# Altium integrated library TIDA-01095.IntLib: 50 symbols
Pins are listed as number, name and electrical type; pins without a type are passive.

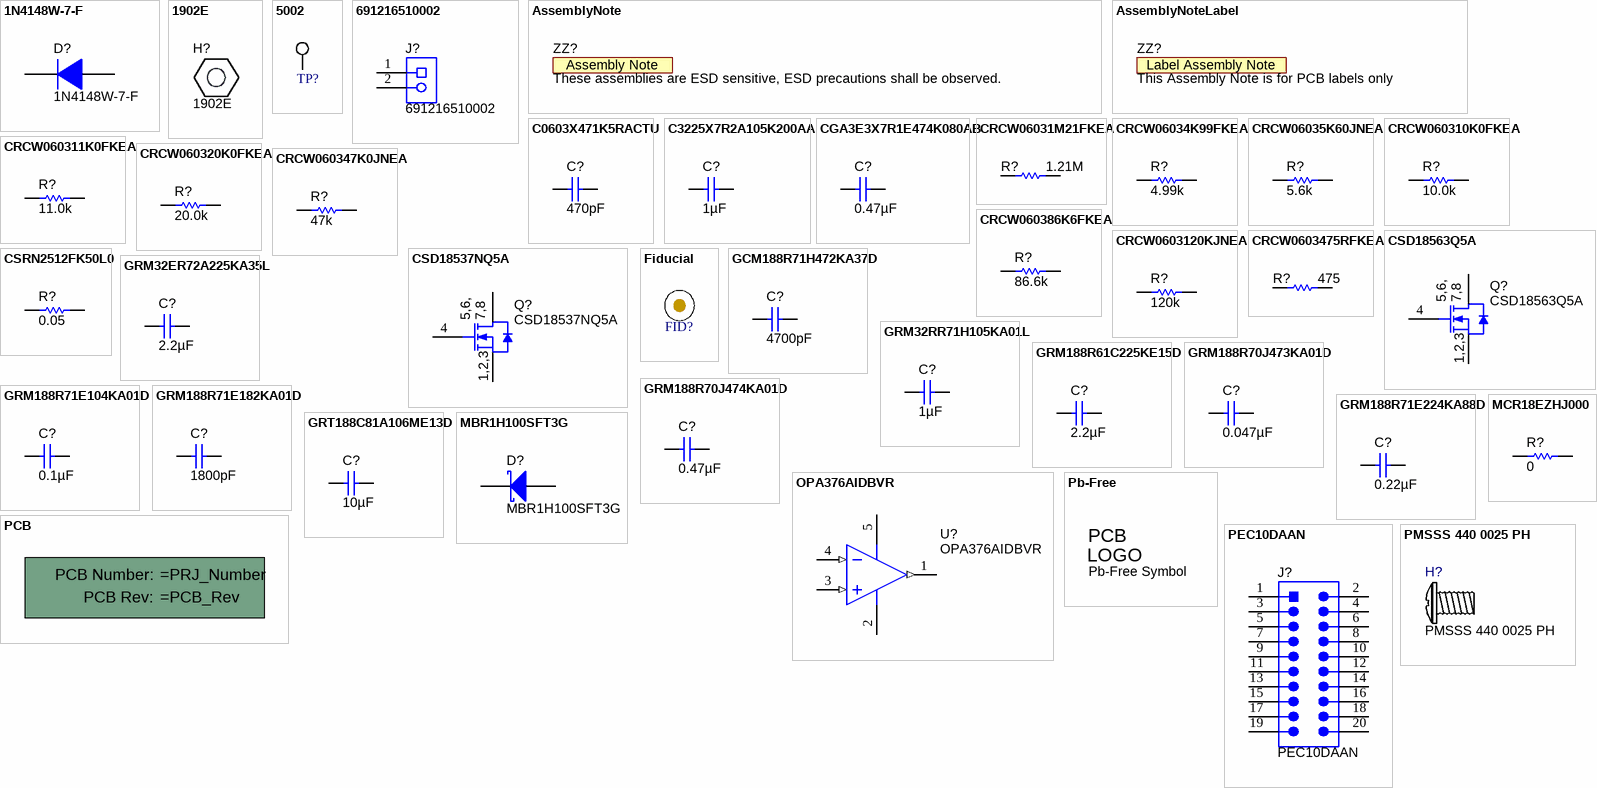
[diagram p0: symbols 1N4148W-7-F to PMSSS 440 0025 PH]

## 1N4148W-7-F
designator D?
Diode, Ultrafast, 100 V, 0.15 A, SOD-123; Manufacturer: Diodes Inc.; U/M: EA; Vf_V: 1.25; Value: 100V; Value1: 0.15A; Value2: 1.25V; Io_A: 0.15; Vr_V: 100; TJmax_C: 150; AEC Category: Q101
signal-integrity model Diode
simulation model 1N4148W
footprint SOD-123
pins: 1 K, 2 A

## 1902E
designator H?
Standoff, Hex, 1"L #4-40 Nylon; Manufacturer: Keystone; CompType: Hardware; SymbolCreator: a0412235
footprint Keystone_1902E

## 5002
designator TP?  (value not drawn)
Test Point, Miniature, White, TH; Manufacturer: Keystone; CompType: Test Point Loop; U/M: EA
footprint Keystone5002
pins: 1

## 691216510002
designator J?
Receptacle, 5.08mm, 2x1, Brass, TH; Manufacturer: Wurth Elektronik; SymbolCreator: a0412235; Pitch_mm: 5.08; Gender: Female; Row_Count: 1; Current_A: 10; Voltage_V: 300; Cert_UL: Y
footprint Wurth_691216510002
pins: 1, 2

## AssemblyNote
designator ZZ?, comment These assemblies are ESD sensitive, ESD precautions shall be observed.  (no BOM)
SymbolCreator: codlsc; CompType: AssemblyNote
footprint AssemblyNote

## AssemblyNoteLabel
designator ZZ?, comment This Assembly Note is for PCB labels only  (no BOM)
SymbolCreator: a0412235
footprint AssemblyNoteLabel

## C0603X471K5RACTU
designator C?  ValueDisplayed: 470pF  (hidden comment: C0603X471K5RACTU)
CAP, CERM, 470 pF, 50 V, +/- 10%, X7R, 0603; Manufacturer: Kemet; Polarized: N; CompType: Capacitor; Value: 470pF; U/M: EA; Cap_F: 0.00000000047; Tolerance_%: 10; Value1: Unknown; VDC_V: 50; Value2: 50V; TaMin_C: -55; TaMax_C: 125; Cap_Case: 0603; AEC Category: Q200
signal-integrity model Cap
simulation model Cap
footprint 0603
footprint 0603M
footprint 0603L
footprint 0603_HV
footprint 0603S
pins: 1, 2

## C3225X7R2A105K200AA
designator C?  ValueDisplayed: 1µF  (hidden comment: C3225X7R2A105K200AA)
CAP, CERM, 1 µF, 100 V, +/- 10%, X7R, 1210; Manufacturer: TDK; Polarized: N; CompType: Capacitor; Value: 1uF; U/M: EA; Cap_F: 0.000001; Tolerance_%: 10; Value1: Unknown; VDC_V: 100; Value2: 100V; TaMin_C: -55; TaMax_C: 125; Cap_Case: 1210; AEC Category: Q200
signal-integrity model Cap
simulation model Cap
footprint 1210
footprint 1210M
footprint 1210L
pins: 1, 2

## CGA3E3X7R1E474K080AB
designator C?  ValueDisplayed: 0.47µF  (hidden comment: CGA3E3X7R1E474K080AB)
CAP, CERM, 0.47 µF, 25 V, +/- 10%, X7R, AEC-Q200 Grade 1, 0603; Manufacturer: TDK; Polarized: N; CompType: Capacitor; Value: 0.47uF; U/M: EA; Cap_F: 0.00000047; Tolerance_%: 10; Value1: Unknown; VDC_V: 25; Value2: 25V; TaMin_C: -55; TaMax_C: 125; Cap_Case: 0603; AEC Category: Q200; AEC Qualified: Y; AEC Grade: 1
signal-integrity model Cap
simulation model Cap
footprint 0603
footprint 0603M
footprint 0603L
footprint 0603_HV
footprint 0603S
pins: 1, 2

## CRCW06031M21FKEA
designator R?  ValueDisplayed: 1.21M  (hidden comment: CRCW06031M21FKEA)
RES, 1.21 M, 1%, 0.1 W, 0603; Manufacturer: Vishay-Dale; CompType: Resistor; Value: 1.21Meg; Res_ohm: 1210000; Value_Code: 1M21; Tolerance_%: 1; Power_W: 0.1; Value2: 0.1W; VDC_V: 75; TempCo: 100 ppm/C; EIA_Code: E96; U/M: EA; AEC Category: Q200
signal-integrity model Resistor
simulation model Resistor
footprint 0603
footprint 0603M
footprint 0603L
footprint 0603_HV
footprint 0603S
pins: 1, 2

## CRCW06034K99FKEA
designator R?  ValueDisplayed: 4.99k  (hidden comment: CRCW06034K99FKEA)
RES, 4.99 k, 1%, 0.1 W, 0603; Manufacturer: Vishay-Dale; CompType: Resistor; Value: 4.99k; Res_ohm: 4990; Value_Code: 4k99; Tolerance_%: 1; Power_W: 0.1; Value2: 0.1W; VDC_V: 75; TempCo: 100 ppm/C; EIA_Code: E96; U/M: EA; AEC Category: Q200; SizeArea_mm2: 1.28; SizeX_mm: 1.6; SizeY_mm: 0.8
signal-integrity model Resistor
simulation model Resistor
footprint 0603
footprint 0603M
footprint 0603L
footprint 0603_HV
footprint 0603S
pins: 1, 2

## CRCW06035K60JNEA
designator R?  ValueDisplayed: 5.6k  (hidden comment: CRCW06035K60JNEA)
RES, 5.6 k, 5%, 0.1 W, 0603; Manufacturer: Vishay-Dale; CompType: Resistor; Value: 5.6k; Res_ohm: 5600; Value_Code: 5k60; Tolerance_%: 5; Power_W: 0.1; Value2: 0.1W; VDC_V: 75; TempCo: 200 ppm/C; EIA_Code: E24; U/M: EA; AEC Category: Q200; SizeArea_mm2: 1.28; SizeX_mm: 1.6; SizeY_mm: 0.8; SizeZ_mm: 1
signal-integrity model Resistor
simulation model Resistor
footprint 0603
footprint 0603M
footprint 0603L
footprint 0603_HV
footprint 0603S
pins: 1, 2

## CRCW060310K0FKEA
designator R?  ValueDisplayed: 10.0k  (hidden comment: CRCW060310K0FKEA)
RES, 10.0 k, 1%, 0.1 W, 0603; Manufacturer: Vishay-Dale; CompType: Resistor; Value: 10.0k; Res_ohm: 10000; Value_Code: 10k0; Tolerance_%: 1; Power_W: 0.1; Value2: 0.1W; VDC_V: 75; TempCo: 100 ppm/C; EIA_Code: E96; U/M: EA; AEC Category: Q200
signal-integrity model Resistor
simulation model Resistor
footprint 0603
footprint 0603M
footprint 0603L
footprint 0603_HV
footprint 0603S
pins: 1, 2

## CRCW060311K0FKEA
designator R?  ValueDisplayed: 11.0k  (hidden comment: CRCW060311K0FKEA)
RES, 11.0 k, 1%, 0.1 W, 0603; Manufacturer: Vishay-Dale; CompType: Resistor; Value: 11.0k; Res_ohm: 11000; Value_Code: 11k0; Tolerance_%: 1; Power_W: 0.1; Value2: 0.1W; VDC_V: 75; TempCo: 100 ppm/C; EIA_Code: E96; U/M: EA; AEC Category: Q200; SizeArea_mm2: 1.28; SizeX_mm: 1.6; SizeY_mm: 0.8
signal-integrity model Resistor
simulation model Resistor
footprint 0603
footprint 0603M
footprint 0603L
footprint 0603_HV
footprint 0603S
pins: 1, 2

## CRCW060320K0FKEA
designator R?  ValueDisplayed: 20.0k  (hidden comment: CRCW060320K0FKEA)
RES, 20.0 k, 1%, 0.1 W, 0603; Manufacturer: Vishay-Dale; CompType: Resistor; Value: 20.0k; Res_ohm: 20000; Value_Code: 20k0; Tolerance_%: 1; Power_W: 0.1; Value2: 0.1W; VDC_V: 75; TempCo: 100 ppm/C; EIA_Code: E96; U/M: EA; AEC Category: Q200
signal-integrity model Resistor
simulation model Resistor
footprint 0603
footprint 0603M
footprint 0603L
footprint 0603_HV
footprint 0603S
pins: 1, 2

## CRCW060347K0JNEA
designator R?  ValueDisplayed: 47k  (hidden comment: CRCW060347K0JNEA)
RES, 47 k, 5%, 0.1 W, 0603; Manufacturer: Vishay-Dale; CompType: Resistor; Value: 47k; Res_ohm: 47000; Value_Code: 47k0; Tolerance_%: 5; Power_W: 0.1; Value2: 0.1W; VDC_V: 75; TempCo: 200 ppm/C; EIA_Code: E24; U/M: EA; AEC Category: Q200; SizeArea_mm2: 1.28; SizeX_mm: 1.6; SizeY_mm: 0.8; SizeZ_mm: 1
signal-integrity model Resistor
simulation model Resistor
footprint 0603
footprint 0603M
footprint 0603L
footprint 0603_HV
footprint 0603S
pins: 1, 2

## CRCW060386K6FKEA
designator R?  ValueDisplayed: 86.6k  (hidden comment: CRCW060386K6FKEA)
RES, 86.6 k, 1%, 0.1 W, 0603; Manufacturer: Vishay-Dale; CompType: Resistor; Value: 86.6k; Res_ohm: 86600; Value_Code: 86k6; Tolerance_%: 1; Power_W: 0.1; Value2: 0.1W; VDC_V: 75; TempCo: 100 ppm/C; EIA_Code: E96; U/M: EA; AEC Category: Q200
signal-integrity model Resistor
simulation model Resistor
footprint 0603
footprint 0603M
footprint 0603L
footprint 0603_HV
footprint 0603S
pins: 1, 2

## CRCW0603120KJNEA
designator R?  ValueDisplayed: 120k  (hidden comment: CRCW0603120KJNEA)
RES, 120 k, 5%, 0.1 W, 0603; Manufacturer: Vishay-Dale; CompType: Resistor; Value: 120k; Res_ohm: 120000; Tolerance_%: 5; Power_W: 0.1; Value2: 0.1W; VDC_V: 75; TempCo: 200 ppm/C; EIA_Code: E24; U/M: EA; AEC Category: Q200; SizeArea_mm2: 1.28; SizeX_mm: 1.6; SizeY_mm: 0.8; SizeZ_mm: 1
signal-integrity model Resistor
simulation model Resistor
footprint 0603
footprint 0603M
footprint 0603L
footprint 0603_HV
footprint 0603S
pins: 1, 2

## CRCW0603475RFKEA
designator R?  ValueDisplayed: 475  (hidden comment: CRCW0603475RFKEA)
RES, 475, 1%, 0.1 W, 0603; Manufacturer: Vishay-Dale; CompType: Resistor; Value: 475; Value_Code: 475R; Tolerance_%: 1; Power_W: 0.1; Value2: 0.1W; VDC_V: 75; TempCo: 100 ppm/C; EIA_Code: E96; U/M: EA; AEC Category: Q200
signal-integrity model Resistor
simulation model Resistor
footprint 0603
footprint 0603M
footprint 0603L
footprint 0603_HV
footprint 0603S
pins: 1, 2

## CSD18537NQ5A
designator Q?
MOSFET, N-CH, 60 V, 50 A, SON 5x6mm; Manufacturer: Texas Instruments; Alternate Manufacturer: None; U/M: EA; ChType: N; Value: 60V; VdsMax_V: 60; Value1: 0.036 ohm; Rdson45_ohm: 0.036; Value2: 14 nC; QgTyp_nC: 14; Vgs_V: 20; IdsMax_A: 50; AEC Category: Q101; SizeAreaWB_mm2: 55.2; SizeArea_mm2: 29.4; SizeX_mm: 6; SizeY_mm: 4.9; SizeZ_mm: 1
footprint TRANS_NexFET_Q5A
pins: 1 S, 2 S, 3 S, 4 G, 5 D, 6 D, 7 D, 8 D, 9 D

## CSD18563Q5A
designator Q?
MOSFET, N-CH, 60 V, 15 A, SON 5x6mm; Manufacturer: Texas Instruments; Alternate Manufacturer: None; U/M: EA; ChType: N; Value: 60V; VdsMax_V: 60; Value1: 0.0086 ohm; Rdson45_ohm: 0.0086; Value2: 15 nC; QgTyp_nC: 15; Vgs_V: 20; AEC Category: Q101
footprint TRANS_NexFET_Q5A
pins: 1 S, 2 S, 3 S, 4 G, 5 D, 6 D, 7 D, 8 D, 9 D

## CSRN2512FK50L0
designator R?  ValueDisplayed: 0.05  (hidden comment: CSRN2512FK50L0)
RES, 0.05, 1%, 2 W, 2512; Manufacturer: Stackpole Electronics Inc; CompType: Resistor; Value: 0.05; Value_Code: R050; Tolerance_%: 1; Power_W: 2; Value2: 2W; TempCo: 200 ppm/C; EIA_Code: E96; U/M: EA; AEC Category: Q200
signal-integrity model Resistor
simulation model Resistor
footprint 2512
footprint 2512M
footprint 2512L
pins: 1, 2

## Fiducial
designator FID?  (value not drawn)
Fiducial mark.  There is nothing to buy or mount.; SymbolCreator: codlsc
footprint Fiducial10-30
footprint Fiducial10-20
footprint Fiducial15-30
footprint Fiducial20-40
footprint Fiducial6.4-20

## GCM188R71H472KA37D
designator C?  ValueDisplayed: 4700pF  (hidden comment: GCM188R71H472KA37D)
CAP, CERM, 4700 pF, 50 V, +/- 10%, X7R, AEC-Q200 Grade 1, 0603; Manufacturer: MuRata; Polarized: N; CompType: Capacitor; Value: 4700pF; U/M: EA; Cap_F: 0.0000000047; Tolerance_%: 10; Value1: Unknown; VDC_V: 50; Value2: 50V; TaMin_C: -55; TaMax_C: 125; Cap_Case: 0603; AEC Category: Q200; AEC Qualified: Y; AEC Grade: 1
signal-integrity model Cap
simulation model Cap
footprint 0603
footprint 0603M
footprint 0603L
footprint 0603_HV
footprint 0603S
pins: 1, 2

## GRM32ER72A225KA35L
designator C?  ValueDisplayed: 2.2µF  (hidden comment: GRM32ER72A225KA35L)
CAP, CERM, 2.2 µF, 100 V, +/- 10%, X7R, 1210; Manufacturer: MuRata; Polarized: N; CompType: Capacitor; Value: 2.2uF; U/M: EA; Cap_F: 0.0000022; Tolerance_%: 10; ESR_ohm: 0.007; Value1: 0.007 ohm; VDC_V: 100; Value2: 100V; IRMS_A: 4.4; TaMin_C: -55; TaMax_C: 125; Cap_Case: 1210; AEC Category: Q200
signal-integrity model Cap
simulation model Cap
footprint 1210_270
footprint 1210_270M
footprint 1210_270L
pins: 1, 2

## GRM32RR71H105KA01L
designator C?  ValueDisplayed: 1µF  (hidden comment: GRM32RR71H105KA01L)
CAP, CERM, 1 µF, 50 V, +/- 10%, X7R, 1210; Manufacturer: MuRata; Polarized: N; CompType: Capacitor; Value: 1uF; U/M: EA; Cap_F: 0.000001; Tolerance_%: 10; ESR_ohm: 0.003; Value1: 0.003 ohm; VDC_V: 50; Value2: 50V; TaMin_C: -55; TaMax_C: 125; Cap_Case: 1210; AEC Category: Q200
signal-integrity model Cap
simulation model Cap
footprint 1210_200
footprint 1210_200M
footprint 1210_200L
pins: 1, 2

## GRM188R61C225KE15D
designator C?  ValueDisplayed: 2.2µF  (hidden comment: GRM188R61C225KE15D)
CAP, CERM, 2.2 µF, 16 V, +/- 10%, X5R, 0603; Manufacturer: MuRata; Polarized: N; CompType: Capacitor; Value: 2.2uF; U/M: EA; Cap_F: 0.0000022; Tolerance_%: 10; Value1: Unknown; VDC_V: 16; Value2: 16V; TaMin_C: -55; TaMax_C: 85; Cap_Case: 0603; AEC Category: Q200
signal-integrity model Cap
simulation model Cap
footprint 0603
footprint 0603M
footprint 0603L
footprint 0603_HV
footprint 0603S
pins: 1, 2

## GRM188R70J473KA01D
designator C?  ValueDisplayed: 0.047µF  (hidden comment: GRM188R70J473KA01D)
CAP, CERM, 0.047 µF, 6.3 V, +/- 10%, X7R, 0603; Manufacturer: MuRata; Polarized: N; CompType: Capacitor; Value: 0.047uF; U/M: EA; Cap_F: 0.000000047; Tolerance_%: 10; Value1: Unknown; VDC_V: 6.3; Value2: 6.3V; TaMin_C: -55; TaMax_C: 125; Cap_Case: 0603; AEC Category: Q200
signal-integrity model Cap
simulation model Cap
footprint 0603
footprint 0603M
footprint 0603L
footprint 0603_HV
footprint 0603S
pins: 1, 2

## GRM188R70J474KA01D
designator C?  ValueDisplayed: 0.47µF  (hidden comment: GRM188R70J474KA01D)
CAP, CERM, 0.47 µF, 6.3 V, +/- 10%, X7R, 0603; Manufacturer: MuRata; Polarized: N; CompType: Capacitor; Value: 0.47uF; U/M: EA; Cap_F: 0.00000047; Tolerance_%: 10; Value1: Unknown; VDC_V: 6.3; Value2: 6.3V; TaMin_C: -55; TaMax_C: 125; Cap_Case: 0603; AEC Category: Q200
signal-integrity model Cap
simulation model Cap
footprint 0603
footprint 0603M
footprint 0603L
footprint 0603_HV
footprint 0603S
pins: 1, 2

## GRM188R71E104KA01D
designator C?  ValueDisplayed: 0.1µF  (hidden comment: GRM188R71E104KA01D)
CAP, CERM, 0.1 µF, 25 V, +/- 10%, X7R, 0603; Manufacturer: MuRata; Polarized: N; CompType: Capacitor; Value: 0.1uF; U/M: EA; Cap_F: 0.0000001; Tolerance_%: 10; Value1: Unknown; VDC_V: 25; Value2: 25V; TaMin_C: -55; TaMax_C: 125; Cap_Case: 0603; AEC Category: Q200
signal-integrity model Cap
simulation model Cap
footprint 0603
footprint 0603M
footprint 0603L
footprint 0603_HV
footprint 0603S
pins: 1, 2

## GRM188R71E182KA01D
designator C?  ValueDisplayed: 1800pF  (hidden comment: GRM188R71E182KA01D)
CAP, CERM, 1800 pF, 25 V, +/- 10%, X7R, 0603; Manufacturer: MuRata; Polarized: N; CompType: Capacitor; Value: 1800pF; U/M: EA; Cap_F: 0.0000000018; Tolerance_%: 10; Value1: Unknown; VDC_V: 25; Value2: 25V; TaMin_C: -55; TaMax_C: 125; Cap_Case: 0603; AEC Category: Q200; SizeArea_mm2: 1.28; SizeAreaWB_mm2: 4.68; SizeX_mm: 1.6; SizeY_mm: 0.8; SizeZ_mm: 1
signal-integrity model Cap
simulation model Cap
footprint 0603
footprint 0603M
footprint 0603L
footprint 0603_HV
footprint 0603S
pins: 1, 2

## GRM188R71E224KA88D
designator C?  ValueDisplayed: 0.22µF  (hidden comment: GRM188R71E224KA88D)
CAP, CERM, 0.22 µF, 25 V, +/- 10%, X7R, 0603; Manufacturer: MuRata; Polarized: N; CompType: Capacitor; Value: 0.22uF; U/M: EA; Cap_F: 0.00000022; Tolerance_%: 10; Value1: Unknown; VDC_V: 25; Value2: 25V; TaMin_C: -55; TaMax_C: 125; Cap_Case: 0603; AEC Category: Q200
signal-integrity model Cap
simulation model Cap
footprint 0603
footprint 0603M
footprint 0603L
footprint 0603_HV
footprint 0603S
pins: 1, 2

## GRT188C81A106ME13D
designator C?  ValueDisplayed: 10µF  (hidden comment: GRT188C81A106ME13D)
CAP, CERM, 10 µF, 10 V, +/- 20%, X6S, AEC-Q200 Grade 2, 0603; Manufacturer: MuRata; Polarized: N; CompType: Capacitor; Value: 10uF; U/M: EA; Cap_F: 0.00001; Tolerance_%: 20; Value1: Unknown; VDC_V: 10; Value2: 10V; TaMin_C: -55; TaMax_C: 105; Cap_Case: 0603; AEC Category: Q200; AEC Qualified: Y; AEC Grade: 2
signal-integrity model Cap
simulation model Cap
footprint 0603
footprint 0603M
footprint 0603L
footprint 0603_HV
footprint 0603S
pins: 1, 2

## MBR1H100SFT3G
designator D?
Diode, Schottky, 100 V, 1 A, SOD-123FL; Manufacturer: ON Semiconductor; U/M: EA; Vf_V: 0.76; Value: 100V; Value1: 1A; Value2: 0.76V; Io_A: 1; Vr_V: 100; TJmax_C: 175; RJC_CperW: 85; SizeAreaWB_mm2: 13.44; SizeArea_mm2: 6.84; SizeX_mm: 3.8; SizeY_mm: 1.8; AEC Category: Q101
signal-integrity model Diode
footprint SOD-123FL
pins: 1 K, 2 A

## MCR18EZHJ000
designator R?  ValueDisplayed: 0  (hidden comment: MCR18EZHJ000)
RES, 0, 5%, 0.25 W, 1206; Manufacturer: Rohm; CompType: Resistor; Value: 0; Value_Code: 0000; Tolerance_%: 5; Power_W: 0.25; Value2: 0.25W; VDC_V: 200; TempCo: 200 ppm/C; EIA_Code: E24; U/M: EA; AEC Category: Q200
signal-integrity model Resistor
simulation model Resistor
footprint 1206
footprint 1206M
footprint 1206L
pins: 1, 2

## OPA376AIDBVR
designator U?
Precision, Low Noise, Low Iq Operational Amplifier, 2.2 to 5.5 V, -40 to 125 degC, 5-pin SOT23 (DBV0005A), Green (RoHS & no Sb/Br); Manufacturer: Texas Instruments; Alternate PartNumber: Equivalent; CMRR(Min)(dB): 76; IIB(Max)(pA): 10; Iq per channel(Max)(mA): 0.95; Number of Channels: 1; Offset Drift(Typ)(uV/C): 0.32; Slew Rate(Typ)(V/us): 2; Sub Family: Low Input Bias Current Amp (<=10pA), Low Noise Amp (<=10nV/rtHz), Low Offset Voltage Amplifier (<=500uV), Low Supply Voltage Amplifier (<=2.7V), Precision Amplifier; Total Supply Voltage(Max)(+5V is 5, +/-5V is 10): 5.5; Total Supply Voltage(Min)(+5V is 5, +/-5V is 10): 2.2; Vio (25C)(Max)(mV): 0.025; Vn at 1kHz(Typ)(nV/rtHz): 7.5
footprint DBV0005A_N (SOT23, 5-Leads, Body 2.9x1.6mm, Pitch 0.95mm, IPC Medium Density)
footprint DBV0005A_L (SOT23, 5-Leads, Body 2.9x1.6mm, Pitch 0.95mm, IPC Low Density)
footprint DBV0005A_M (SOT23, 5-Leads, Body 2.9x1.6mm, Pitch 0.95mm, IPC Low Density)
pins: 1 OUT (out), 2 V- (power), 3 IN+ (in), 4 IN- (in), 5 V+ (power)

## Pb-Free
designator Logo?, comment Pb-Free Symbol  (no BOM)
SymbolCreator: a0412235
footprint Pb-Free_Overlay_Medium
footprint Pb-Free_Overlay_Small

## PCB
designator !PCB?, comment Printed Circuit Board  (value not drawn)  (mechanical)
Manufacturer: Any; SymbolCreator: a0412235; CompType: PCB
1 alternate drawing of the same symbol

## PEC10DAAN
designator J?
Header, 100mil, 10x2, TH; Manufacturer: Sullins Connector Solutions; SymbolCreator: a0412235; U/M: EA
footprint SULLINS_PEC10DAAN
pins: 1, 2, 3, 4, 5, 6, 7, 8, 9, 10, 11, 12, 13, 14, 15, 16, 17, 18, 19, 20

## PMSSS 440 0025 PH
designator H?
MACHINE SCREW PAN PHILLIPS 4-40; Manufacturer: B&F Fastener Supply; CompType: Standoff; SymbolCreator: a0412235
footprint B_F_PMSSS4400025PH

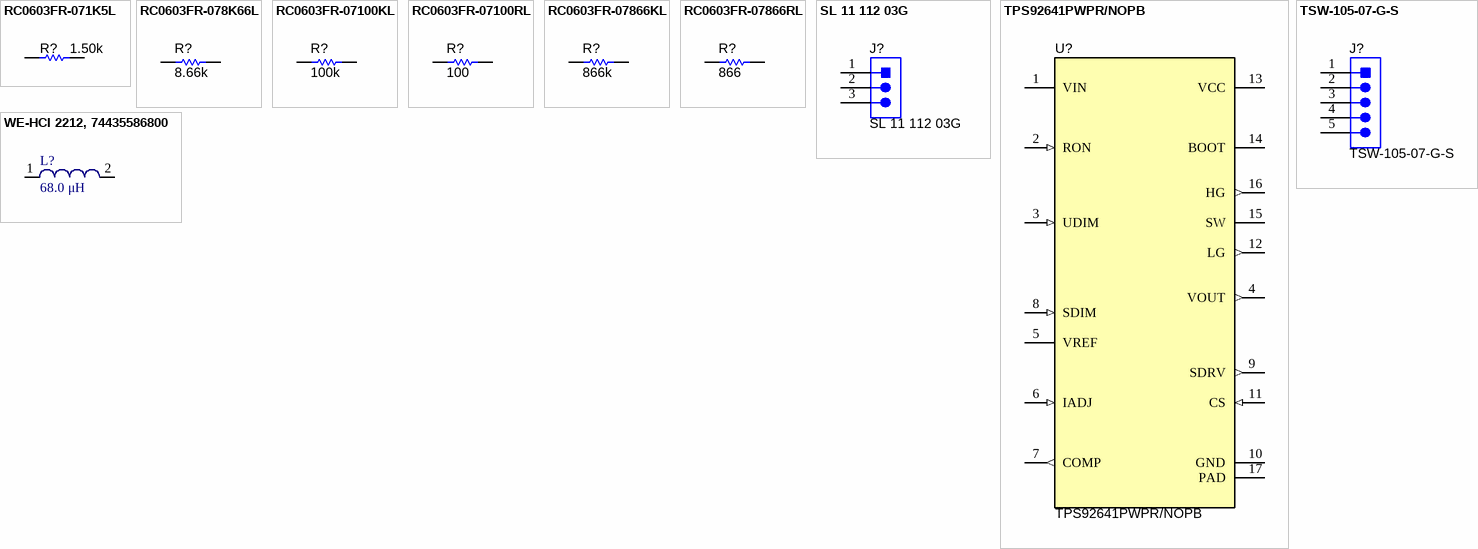
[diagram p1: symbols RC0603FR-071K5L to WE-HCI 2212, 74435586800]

## RC0603FR-071K5L
designator R?  ValueDisplayed: 1.50k  (hidden comment: RC0603FR-071K5L)
RES, 1.50 k, 1%, 0.1 W, 0603; Manufacturer: Yageo America; CompType: Resistor; Value: 1.50k; Res_ohm: 1500; Value_Code: 1k50; Tolerance_%: 1; Power_W: 0.1; Value2: 0.1W; VDC_V: 150; TempCo: 200 ppm/C; EIA_Code: E96; U/M: EA; AEC Category: Q200
signal-integrity model Resistor
simulation model Resistor
footprint 0603
footprint 0603M
footprint 0603L
footprint 0603_HV
footprint 0603S
pins: 1, 2

## RC0603FR-078K66L
designator R?  ValueDisplayed: 8.66k  (hidden comment: RC0603FR-078K66L)
RES, 8.66 k, 1%, 0.1 W, 0603; Manufacturer: Yageo America; CompType: Resistor; Value: 8.66k; Res_ohm: 8660; Value_Code: 8k66; Tolerance_%: 1; Power_W: 0.1; Value2: 0.1W; VDC_V: 150; TempCo: 200 ppm/C; EIA_Code: E96; U/M: EA; AEC Category: Q200
signal-integrity model Resistor
simulation model Resistor
footprint 0603
footprint 0603M
footprint 0603L
footprint 0603_HV
footprint 0603S
pins: 1, 2

## RC0603FR-07100KL
designator R?  ValueDisplayed: 100k  (hidden comment: RC0603FR-07100KL)
RES, 100 k, 1%, 0.1 W, 0603; Manufacturer: Yageo America; CompType: Resistor; Value: 100k; Res_ohm: 100000; Tolerance_%: 1; Power_W: 0.1; Value2: 0.1W; VDC_V: 150; TempCo: 200 ppm/C; EIA_Code: E96; U/M: EA; AEC Category: Q200
signal-integrity model Resistor
simulation model Resistor
footprint 0603
footprint 0603M
footprint 0603L
footprint 0603_HV
footprint 0603S
pins: 1, 2

## RC0603FR-07100RL
designator R?  ValueDisplayed: 100  (hidden comment: RC0603FR-07100RL)
RES, 100, 1%, 0.1 W, 0603; Manufacturer: Yageo America; CompType: Resistor; Value: 100; Value_Code: 100R; Tolerance_%: 1; Power_W: 0.1; Value2: 0.1W; VDC_V: 150; TempCo: 200 ppm/C; EIA_Code: E96; U/M: EA; AEC Category: Q200
signal-integrity model Resistor
simulation model Resistor
footprint 0603
footprint 0603M
footprint 0603L
footprint 0603_HV
footprint 0603S
pins: 1, 2

## RC0603FR-07866KL
designator R?  ValueDisplayed: 866k  (hidden comment: RC0603FR-07866KL)
RES, 866 k, 1%, 0.1 W, 0603; Manufacturer: Yageo America; CompType: Resistor; Value: 866k; Res_ohm: 866000; Tolerance_%: 1; Power_W: 0.1; Value2: 0.1W; VDC_V: 150; TempCo: 200 ppm/C; EIA_Code: E96; U/M: EA; AEC Category: Q200
signal-integrity model Resistor
simulation model Resistor
footprint 0603
footprint 0603M
footprint 0603L
footprint 0603_HV
footprint 0603S
pins: 1, 2

## RC0603FR-07866RL
designator R?  ValueDisplayed: 866  (hidden comment: RC0603FR-07866RL)
RES, 866, 1%, 0.1 W, 0603; Manufacturer: Yageo America; CompType: Resistor; Value: 866; Value_Code: 866R; Tolerance_%: 1; Power_W: 0.1; Value2: 0.1W; VDC_V: 150; TempCo: 200 ppm/C; EIA_Code: E96; U/M: EA; AEC Category: Q200
signal-integrity model Resistor
simulation model Resistor
footprint 0603
footprint 0603M
footprint 0603L
footprint 0603_HV
footprint 0603S
pins: 1, 2

## SL 11 112 03G
designator J?
Header, 2.54mm, 3x1, Gold, TH; Manufacturer: Fischer Elektronik; SymbolCreator: a0799628
footprint Fischer_SL-11-112-03G
pins: 1, 2, 3
3 alternate drawings of the same symbol

## TPS92641PWPR/NOPB
designator U?
Synchronous Buck Controller for Precision Dimming LED Drivers, PWP0016A; Alternate PartNumber: TPS92641PWP/NOPB; Manufacturer: Texas Instruments; SymbolCreator: a0411947; SizeX_mm: 6.4; SizeY_mm: 5; SizeZ_mm: 1.2; CompType: IC; U/M: EA
footprint PWP0016A_N
footprint PWP0016A_M
footprint PWP0016A_L
pins: 1 VIN (power), 2 RON (in), 3 UDIM (in), 4 VOUT (out), 5 VREF (power), 6 IADJ (in), 7 COMP (out), 8 SDIM (in), 9 SDRV (out), 10 GND (power), 11 CS (in), 12 LG (out), 13 VCC (power), 14 BOOT (power), 15 SW (power), 16 HG (out), 17 PAD (power)

## TSW-105-07-G-S
designator J?
Header, 100mil, 5x1, Gold, TH; Manufacturer: Samtec; SymbolCreator: a0412235; U/M: EA
footprint TSW-105-07-G-S
footprint TSW-105-07-X-S
pins: 1, 2, 3, 4, 5

## WE-HCI 2212, 74435586800
designator L?, comment 68.0 μH
WE-HCI SMD Flat Wire High Current Inductor, Inductance = 68.0 μH; PartNumber: 74435586800; Manufacturer: Wurth Elektronik
footprint WE-HCI 2212
pins: 1, 2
